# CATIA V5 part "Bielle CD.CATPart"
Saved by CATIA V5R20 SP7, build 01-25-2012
Part number: Bielle CD
Publications: "Point.1", "Point.2", "Droite.2", "Droite.3"
Bounding box of the stored display mesh (mm): x -10 to 10, y 0 to 0, z -450 to 0
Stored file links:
  U:\IAO\IAO\IAO\Bielle CD.CATPart
  U:\IAO\IAO\IAO\Squelette.CATProduct
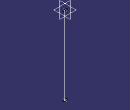
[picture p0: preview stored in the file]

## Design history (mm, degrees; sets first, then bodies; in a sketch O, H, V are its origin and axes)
External parameters (linked from other documents)
  `External.Longueur AB` = 240 mm
  `External.Longueur X4` = 450 mm
  `External.Longueur Demi Pivot` = 10 mm
Body1 (main body)
  Point1: (0, 0, 0)
  Line1: type Normal, RefPoint Point1, RefSkin xy-plane, Start 0, End 450 {= `External.Longueur X4`}
  Point2: (0, 0, 0), relative to vertex of Line1
  Line2: type PtDir, RefPoint Point1, Direction yz-plane, Start -10, End 10 {= `External.Longueur Demi Pivot`}
  Line3: type PtDir, RefPoint Point2, Direction yz-plane, Start -10, End 10 {= `External.Longueur Demi Pivot`}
